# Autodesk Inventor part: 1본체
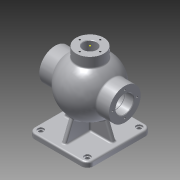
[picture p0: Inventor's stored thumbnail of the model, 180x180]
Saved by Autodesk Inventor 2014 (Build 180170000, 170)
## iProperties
Created: 2017-01
Part Number: 1본체
Material: Aluminum 6061
Document SubType Name: Modeling
Designer: ksu
Density: 2.71 g/cm^3
Appearance: Aluminum - Flat
Author: ksu
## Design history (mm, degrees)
sketch "Sketch1"
  geometry: L1 (50.782, 15.171)-(-50.782, -15.171); A1 r 53 centre (0, 0) between (50.782, 15.171) and (-50.782, -15.171); 1 further point
  constraints: 2 end point, 2 point on circle, 1 centre point, 1 coincident, 1 midpoint
  dimensions: "d0" = 106 diameter of A1
revolve "Revolution1" sketch "Sketch1" stored, may be unused: angle "d1" = 90 deg
workplane "Work Plane1"
sketch "Sketch2"
  geometry: C1 r 31 at (0, 0); 1 further point
  constraints: 1 centre point, 1 coincident
  dimensions: "d3" = 62 diameter of C1
extrude "Extrusion1" join sketch "Sketch2" distance "d4" = 136; taper "d5" = 0 deg
workplane "Work Plane2"
sketch "Sketch3"
  geometry: C1 r 27 at (0, 0); 1 further point
  constraints: 1 centre point, 1 coincident
  dimensions: "d7" = 54 diameter of C1
extrude "Extrusion2" join sketch "Sketch3" distance "d8" = 50; taper "d9" = 0 deg
sketch "Sketch4"
  geometry: 1 further point
workplane "Work Plane3"
sketch "Sketch5"
  geometry: L1 (-57.5, 62.5)-(57.5, 62.5); L2 (57.5, 62.5)-(57.5, -62.5); L3 (57.5, -62.5)-(-57.5, -62.5); L4 (-57.5, -62.5)-(-57.5, 62.5); L5 (-57.5, 62.5)-(57.5, -62.5); L6 (57.5, 62.5)-(-57.5, -62.5); 1 further point
  constraints: 12 end point, 2 midpoint, 2 parallel, 1 horizontal, 1 perpendicular
  dimensions: "d11" = 115 distance of L2.end L3.end; "d12" = 125 distance of L1.end L2.end
extrude "Extrusion3" join sketch "Sketch5" distance "d13" = 10; taper "d14" = 0 deg
sketch "Sketch6"
  geometry: L1 (45.607, 27)-(45.607, -27) reference; L2 (-75, 62.5)-(-75, -62.5) reference; L3 (-85, -62.5)-(-85, 62.5) reference; L4 (-85, 62.5)-(-75, 62.5) reference; L5 (-85, -62.5)-(-75, -62.5) reference; L6 (-75, -62.5)-(-75, -52.5); L7 (-75, -52.5)-(-29.594, -34.155); L8 (-75, 62.5)-(-75, 52.5); L9 (-75, 52.5)-(-29.594, 34.155); L10 (-75, -52.5)-(-75, 52.5); L11 (-29.594, -34.155)-(-29.594, 34.155); C1 r 31 at (0, 0) reference; C2 r 31 at (0, 0) reference; A1 r 53 centre (0, 0) between (45.607, 27) and (45.607, -27) reference; 1 further point
  constraints: 12 end point, 2 point on line, 1 collinear, 1 parallel
  dimensions: "d15" = 10 distance of L2.end L6.end; "d16" = 10 distance of L2.start L8.end
extrude "Extrusion4" join sketch "Sketch6" stored distance "d20" = 8; taper "d21" = 0 deg
sketch "Sketch7"
  geometry: L1 (57.5, -75)-(-57.5, -75) reference; L2 (57.5, -85)-(57.5, -75) reference; L3 (-57.5, -85)-(-57.5, -75) reference; L4 (-57.5, -75)-(-47.5, -75); L5 (-47.5, -75)-(-25.719, -21.091); L6 (57.5, -75)-(47.5, -75); L7 (47.5, -75)-(25.719, -21.091); L8 (-47.5, -75)-(47.5, -75); L9 (-25.719, -21.091)-(25.719, -21.091); A1 r 53 centre (0, 0) between (42.988, 31) and (42.988, -31) reference; 1 further point
  constraints: 12 end point, 2 point on line, 1 collinear, 1 parallel
  dimensions: "d22" = 10 distance of L1.end L4.end; "d23" = 10 distance of L1.start L6.end
extrude "Extrusion5" join sketch "Sketch7" stored distance "d26" = 8; taper "d27" = 0 deg
sketch "Sketch8"
  geometry: L1 (0, 43)-(0, -43); A1 r 43 centre (0, 0) between (0, -43) and (0, 43); 1 further point
  constraints: 2 end point, 2 point on circle, 1 centre point, 1 coincident, 1 vertical
revolve "Revolution2" sketch "Sketch8" stored, may be unused: angle "d29" = 90 deg
sketch "Sketch9"
  geometry: C1 r 31 at (0, 0) reference; C2 r 17.5 at (0, 0)
  constraints: 1 centre point, 1 coincident
  dimensions: "d30" = 35 diameter of C2
extrude "Extrusion6" cut sketch "Sketch9" distance "d31" = 136; taper "d32" = 0 deg
workplane "Work Plane5"
  workplane "Work Plane4"
sketch "Sketch10"
  geometry: C1 r 18.5 at (0, 0); 1 further point
  constraints: 1 centre point, 1 coincident
  dimensions: "d35" = 37 diameter of C1
extrude "Extrusion7" cut sketch "Sketch10" distance "d36" = 1.75; taper "d37" = 0 deg
sketch "Sketch11"
  geometry: C1 r 27 at (0, 0) reference; C2 r 13 at (0, 0)
  constraints: 1 centre point, 1 coincident
  dimensions: "d38" = 26 diameter of C2
extrude "Extrusion8" cut sketch "Sketch11" distance "d39" = 50; taper "d40" = 0 deg
sketch "Sketch12"
  geometry: C1 r 31 at (0, 0) reference; A1 r 22.5 centre (0, 0) between (0, 22.5) and (22.5, 0); 2 further points
  constraints: 4 point on circle, 1 centre point, 1 coincident
  dimensions: "d41" = 45 diameter of A1
hole "Hole1" sketch "Sketch12" at (0, 22.5), (22.5, 0), (0, -22.5), (-22.5, 0) diameter "d42" = 3.459; stored, may be unused: countersink angle "d46" = 90 deg, drill point angle "d48" = 118 deg; dims "d43" = 12, "d44" = 4, "d45" = 2, "d47" = 15
sketch "Sketch13"
  geometry: C1 r 31 at (0, 0) reference; A1 r 24 centre (0, 0) between (0, 24) and (24, 0); 2 further points
  constraints: 4 point on circle, 1 centre point, 1 coincident
  dimensions: "d49" = 48 diameter of A1
hole "Hole2" sketch "Sketch13" at (0, 24), (24, 0), (0, -24), (-24, 0) diameter "d50" = 3.459; stored, may be unused: countersink angle "d54" = 90 deg, drill point angle "d56" = 118 deg; dims "d51" = 16, "d52" = 4, "d53" = 2, "d55" = 19
sketch "Sketch14"
  geometry: C1 r 27 at (0, 0) reference; A1 r 20 centre (0, 0) between (0, 20) and (20, 0); 2 further points
  constraints: 4 point on circle, 1 centre point, 1 coincident
  dimensions: "d57" = 40 diameter of A1
hole "Hole3" sketch "Sketch14" at (20, 0), (0, -20), (-20, 0), (0, 20) diameter "d58" = 3.459; stored, may be unused: countersink angle "d62" = 90 deg, drill point angle "d64" = 118 deg; dims "d59" = 9, "d60" = 4, "d61" = 2, "d63" = 11
sketch "Sketch15"
  geometry: L1 (57.5, 62.5)-(-57.5, 62.5) reference; L2 (-57.5, 62.5)-(-57.5, -62.5) reference; L3 (-57.5, -62.5)-(57.5, -62.5) reference; L4 (57.5, -62.5)-(57.5, 62.5) reference; L5 (-57.5, 0)-(57.5, 0); L6 (0, -62.5)-(0, 62.5); C1 r 4 at (-45.5, 50.5); C2 r 4 at (-45.5, -50.5); C3 r 4 at (45.5, -50.5); C4 r 4 at (45.5, 50.5); 1 further point
  constraints: 4 centre point, 4 end point, 4 midpoint, 3 symmetric about line, 3 other
  dimensions: "d67" = 8 diameter of C1
extrude "Extrusion9" cut sketch "Sketch15" distance "d68" = 10; taper "d69" = 0 deg
sketch "Sketch16"
  geometry: C1 r 4 at (45.5, -50.5) reference; C2 r 4 at (-45.5, -50.5) reference; C3 r 4 at (-45.5, 50.5) reference; C4 r 4 at (45.5, 50.5) reference; C5 r 6 at (-45.5, 50.5); C6 r 6 at (45.5, 50.5); C7 r 6 at (45.5, -50.5); C8 r 6 at (-45.5, -50.5); 1 further point
  constraints: 4 centre point, 4 coincident
  dimensions: "d70" = 12 diameter of C5; "d71" = 12 diameter of C6; "d72" = 12 diameter of C7; "d73" = 12 diameter of C8
extrude "Extrusion10" cut sketch "Sketch16" distance "d74" = 3; taper "d75" = 0 deg
fillet "Fillet1" dims "d76" = 12
fillet "Fillet2" dims "d77" = 3
fillet "Fillet3" dims "d78" = 3
chamfer "Chamfer1" distance "d79" = 1; stored, may be unused: second distance "d80" = 2, angle "d81" = 45 deg
workplane "Work Plane6"
sketch "Sketch17"
  geometry: L1 (-19.522, 59.663)-(20.055, 59.663); L2 (20.055, 59.663)-(20.055, 50.047); L3 (20.055, 50.047)-(-19.522, 50.047); L4 (-19.522, 50.047)-(-19.522, 59.663); L5 (-27, 65)-(27, 65) reference; L6 (-27, 65)-(-27, 47.286) reference; L7 (-68, -31)-(-68, 31) reference; L8 (-44.497, -31)-(-44.497, 31) reference; 2 further points
  constraints: 2 other
emboss "Emboss1" sketch "Sketch17" dims "d0" = 106, "d11" = 115, "d12" = 125, "d84" = 0.5, "d85" = 0
body "Solid1"
node "Projected Loop1"
node "Projected Loop2"
other parameters: "d2" = 68, "d6" = 65, "d10" = -85, "d33" = 68, "d34" = -16
